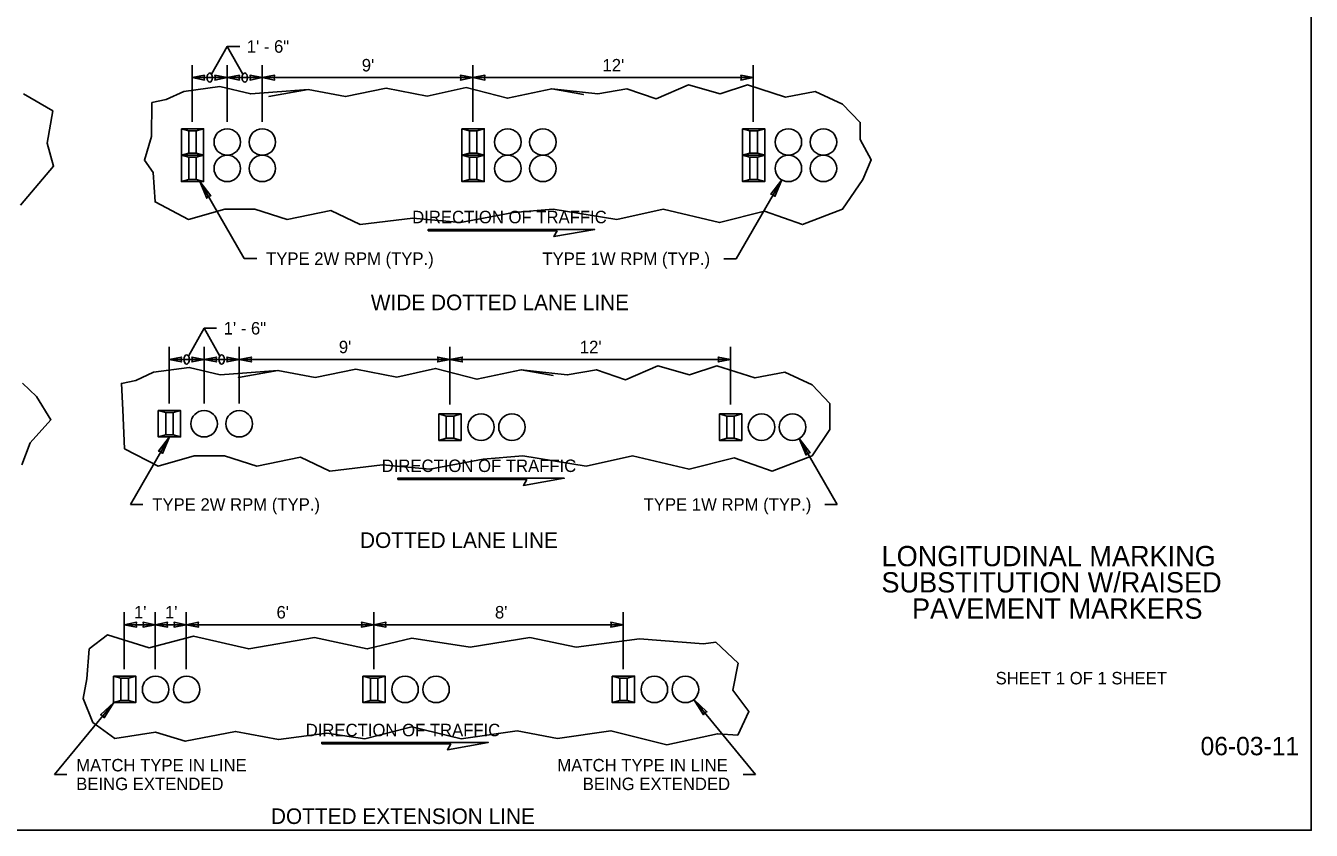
# Model space of a CAD drawing. Extents: x 99862 to 103151, y 100000 to 102076.
# Drawn here: x 101501 to 103151, y 100000 to 101032 of the extents above; entities that cross this region are included whole.
import ezdxf

# ---------------------------------------------------------------- set-up
doc = ezdxf.new("R2010")
doc.units = 0
for name, color, linetype in [('Level 1', 7, 'Continuous'), ('Level 11', 7, 'Continuous'), ('Level 15', 7, 'Continuous'), ('Level 20', 7, 'Continuous'), ('Level 3', 7, 'Continuous'), ('Level 50', 7, 'Continuous'), ('Level 62', 7, 'Continuous')]:
    doc.layers.add(name, color=color, linetype=linetype)

msp = doc.modelspace()

# ---------------------------------------------------------------- linework, layer by layer
at = {"layer": 'Level 1'}
msp.add_lwpolyline([(99862, 99999.5), (103151, 99999.5), (103151, 102075.5), (99862, 102075.5)], close=True, dxfattribs=at)
at = {"layer": 'Level 11'}
for p, q in [((101701.2, 100900), (101710.7, 100897.3)), ((101720.2, 100897.3), (101729.7, 100900)), ((102061.2, 100900), (102070.7, 100897.3)), ((102080.2, 100897.3), (102089.7, 100900)), ((102421.2, 100900), (102430.7, 100897.3)), ((102440.2, 100897.3), (102449.7, 100900)), ((101710.7, 100868.8), (101701.2, 100866.1)), ((101710.7, 100863.4), (101701.2, 100866.1)), ((101701.2, 100866.1), (101729.7, 100866.1)), ((101720.2, 100868.8), (101729.7, 100866.1)), ((101720.2, 100863.4), (101729.7, 100866.1)), ((102070.7, 100868.8), (102061.2, 100866.1)), ((102070.7, 100863.4), (102061.2, 100866.1)), ((102061.2, 100866.1), (102089.7, 100866.1)), ((102080.2, 100868.8), (102089.7, 100866.1)), ((102080.2, 100863.4), (102089.7, 100866.1)), ((102430.7, 100868.8), (102421.2, 100866.1)), ((102430.7, 100863.4), (102421.2, 100866.1)), ((102421.2, 100866.1), (102449.7, 100866.1)), ((102440.2, 100868.8), (102449.7, 100866.1)), ((102440.2, 100863.4), (102449.7, 100866.1)), ((101710.7, 100834.8), (101701.2, 100832.1)), ((101720.2, 100834.8), (101729.7, 100832.1)), ((102070.7, 100834.8), (102061.2, 100832.1)), ((102080.2, 100834.8), (102089.7, 100832.1)), ((102430.7, 100834.8), (102421.2, 100832.1)), ((102440.2, 100834.8), (102449.7, 100832.1)), ((101671.5, 100538.3), (101681.1, 100535.7)), ((101690.6, 100535.7), (101700.1, 100538.3)), ((102031.5, 100533.9), (102041.1, 100531.2)), ((102050.6, 100531.2), (102060.1, 100533.9)), ((102391.5, 100533.9), (102401.1, 100531.2)), ((102410.6, 100531.2), (102420.1, 100533.9)), ((101681.1, 100507.1), (101671.5, 100504.4)), ((101690.6, 100507.1), (101700.1, 100504.4)), ((102041.1, 100502.7), (102031.5, 100500)), ((102050.6, 100502.7), (102060.1, 100500)), ((102401.1, 100502.7), (102391.5, 100500)), ((102410.6, 100502.7), (102420.1, 100500)), ((101614.1, 100197.4), (101623.6, 100194.7)), ((101633.1, 100194.7), (101642.6, 100197.4)), ((101934.1, 100197.4), (101943.6, 100194.7)), ((101953.1, 100194.7), (101962.6, 100197.4)), ((102254.1, 100197.4), (102263.6, 100194.7)), ((102273.1, 100194.7), (102282.6, 100197.4)), ((101623.6, 100166.2), (101614.1, 100163.5)), ((101633.1, 100166.2), (101642.6, 100163.5)), ((101943.6, 100166.2), (101934.1, 100163.5)), ((101953.1, 100166.2), (101962.6, 100163.5)), ((102263.6, 100166.2), (102254.1, 100163.5)), ((102273.1, 100166.2), (102282.6, 100163.5))]:
    msp.add_line(p, q, dxfattribs=at)
for points in [[(101701.2, 100900), (101729.7, 100900), (101729.7, 100832.1), (101701.2, 100832.1)], [(101710.7, 100897.3), (101720.2, 100897.3), (101720.2, 100868.8), (101710.7, 100868.8)], [(102061.2, 100900), (102089.7, 100900), (102089.7, 100832.1), (102061.2, 100832.1)], [(102070.7, 100897.3), (102080.2, 100897.3), (102080.2, 100868.8), (102070.7, 100868.8)], [(102421.2, 100900), (102449.7, 100900), (102449.7, 100832.1), (102421.2, 100832.1)], [(102430.7, 100897.3), (102440.2, 100897.3), (102440.2, 100868.8), (102430.7, 100868.8)], [(101710.7, 100834.8), (101720.2, 100834.8), (101720.2, 100863.4), (101710.7, 100863.4)], [(102070.7, 100834.8), (102080.2, 100834.8), (102080.2, 100863.4), (102070.7, 100863.4)], [(102430.7, 100834.8), (102440.2, 100834.8), (102440.2, 100863.4), (102430.7, 100863.4)], [(101671.5, 100538.3), (101700.1, 100538.3), (101700.1, 100504.4), (101671.5, 100504.4)], [(101681.1, 100535.7), (101690.6, 100535.7), (101690.6, 100507.1), (101681.1, 100507.1)], [(102031.5, 100533.9), (102060.1, 100533.9), (102060.1, 100500), (102031.5, 100500)], [(102041.1, 100531.2), (102050.6, 100531.2), (102050.6, 100502.7), (102041.1, 100502.7)], [(102391.5, 100533.9), (102420.1, 100533.9), (102420.1, 100500), (102391.5, 100500)], [(102401.1, 100531.2), (102410.6, 100531.2), (102410.6, 100502.7), (102401.1, 100502.7)], [(101614.1, 100197.4), (101642.6, 100197.4), (101642.6, 100163.5), (101614.1, 100163.5)], [(101623.6, 100194.7), (101633.1, 100194.7), (101633.1, 100166.2), (101623.6, 100166.2)], [(101934.1, 100197.4), (101962.6, 100197.4), (101962.6, 100163.5), (101934.1, 100163.5)], [(101943.6, 100194.7), (101953.1, 100194.7), (101953.1, 100166.2), (101943.6, 100166.2)], [(102254.1, 100197.4), (102282.6, 100197.4), (102282.6, 100163.5), (102254.1, 100163.5)], [(102263.6, 100194.7), (102273.1, 100194.7), (102273.1, 100166.2), (102263.6, 100166.2)]]:
    msp.add_lwpolyline(points, close=True, dxfattribs=at)
for centre in [(101760, 100883), (101805, 100883), (102120, 100883), (102165, 100883), (102480, 100883), (102525, 100883), (101760, 100849.1), (101805, 100849.1), (102120, 100849.1), (102165, 100849.1), (102480, 100849.1), (102525, 100849.1), (101730.3, 100521.4), (101775.3, 100521.4), (102085.6, 100517), (102125.3, 100517), (102445.6, 100517), (102485.3, 100517), (101668.1, 100180.4), (101707.9, 100180.4), (101988.1, 100180.4), (102027.9, 100180.4), (102308.1, 100180.4), (102347.9, 100180.4)]:
    msp.add_circle(centre, 17, dxfattribs=at)
at = {"layer": 'Level 15'}
for p, q in [((101760, 101005.6), (101776, 101005.6)), ((101715, 100981.6), (101715, 100909)), ((101760, 100981.6), (101760, 100909)), ((101805, 100981.6), (101805, 100909)), ((102075, 100981.6), (102075, 100909)), ((102435, 100981.6), (102435, 100909)), ((101715, 100965.6), (101760, 100965.6)), ((101760, 100965.6), (101805, 100965.6)), ((101805, 100965.6), (102075, 100965.6)), ((102075, 100965.6), (102435, 100965.6)), ((101724.8, 100832.1), (101781.8, 100733.3)), ((102471.5, 100834.4), (102413, 100733.2)), ((101781.8, 100733.3), (101797.8, 100733.3)), ((102397, 100733.2), (102413, 100733.2)), ((101730.4, 100643.9), (101746.4, 100643.9)), ((101685.3, 100619.9), (101685.3, 100547.3)), ((101730.3, 100619.9), (101730.3, 100547.3)), ((101775.3, 100619.9), (101775.3, 100547.3)), ((102045.8, 100619.9), (102045.8, 100545.9)), ((102405.8, 100619.9), (102405.8, 100545.9)), ((101685.3, 100603.9), (101730.3, 100603.9)), ((101730.3, 100603.9), (101775.3, 100603.9)), ((101775.3, 100603.9), (102045.8, 100603.9)), ((102045.8, 100603.9), (102405.8, 100603.9)), ((101685.8, 100504.4), (101635.8, 100417.7)), ((102493.8, 100502.4), (102542.6, 100417.8)), ((101635.8, 100417.7), (101651.8, 100417.7)), ((102542.6, 100417.8), (102526.6, 100417.8)), ((101627.9, 100279.4), (101627.9, 100206.4)), ((101667.6, 100279.4), (101667.6, 100206.4)), ((101707.4, 100279.4), (101707.4, 100206.4)), ((101947.9, 100279.4), (101947.9, 100206.4)), ((102267.9, 100279.4), (102267.9, 100206.4)), ((101627.9, 100263.4), (101667.6, 100263.4)), ((101667.6, 100263.4), (101707.4, 100263.4)), ((101707.4, 100263.4), (101947.9, 100263.4)), ((101947.9, 100263.4), (102267.9, 100263.4)), ((102438, 100071.1), (102358.7, 100167.4)), ((101538.2, 100071.1), (101614.4, 100163.5)), ((101554.2, 100071.1), (101538.2, 100071.1)), ((102422, 100071.1), (102438, 100071.1))]:
    msp.add_line(p, q, dxfattribs=at)
for points in [[(101739.9, 100969.9), (101760, 101005.6), (101780.1, 100969.9)], [(101710.3, 100608.2), (101730.4, 100643.9), (101750.4, 100608.2)]]:
    msp.add_lwpolyline(points, dxfattribs=at)
for points in [[(101715, 100965.6), (101730.7, 100962.5), (101730, 100965.6), (101730.7, 100968.7)], [(101760, 100965.6), (101744.2, 100962.5), (101745, 100965.6), (101744.2, 100968.7)], [(101760, 100965.6), (101775.7, 100962.5), (101775, 100965.6), (101775.7, 100968.7)], [(101805, 100965.6), (101789.2, 100962.5), (101790, 100965.6), (101789.2, 100968.7)], [(101805, 100965.6), (101820.7, 100962.5), (101820, 100965.6), (101820.7, 100968.7)], [(102075, 100965.6), (102059.2, 100968.7), (102060, 100965.6), (102059.2, 100962.5)], [(102075, 100965.6), (102090.7, 100962.5), (102090, 100965.6), (102090.7, 100968.7)], [(102435, 100965.6), (102419.2, 100968.7), (102420, 100965.6), (102419.2, 100962.5)], [(101724.8, 100832.1), (101738.8, 100813.9), (101735.6, 100813.3), (101733.6, 100810.9)], [(102471.5, 100834.4), (102457.5, 100816.1), (102460.6, 100815.6), (102462.7, 100813.2)], [(101685.3, 100603.9), (101701.1, 100600.8), (101700.3, 100603.9), (101701.1, 100607)], [(101730.3, 100603.9), (101714.6, 100600.8), (101715.3, 100603.9), (101714.6, 100607)], [(101730.3, 100603.9), (101746.1, 100600.8), (101745.3, 100603.9), (101746.1, 100607)], [(101775.3, 100603.9), (101759.6, 100600.8), (101760.3, 100603.9), (101759.6, 100607)], [(101775.3, 100603.9), (101791.1, 100600.8), (101790.3, 100603.9), (101791.1, 100607)], [(102045.8, 100603.9), (102030.1, 100607), (102030.8, 100603.9), (102030.1, 100600.8)], [(102045.8, 100603.9), (102061.5, 100600.8), (102060.8, 100603.9), (102061.5, 100607)], [(102405.8, 100603.9), (102390.1, 100607), (102390.8, 100603.9), (102390.1, 100600.8)], [(101685.8, 100504.4), (101671.8, 100486.1), (101674.9, 100485.6), (101677, 100483.2)], [(102493.8, 100502.4), (102502.7, 100481.1), (102504.7, 100483.5), (102507.8, 100484.1)], [(101627.9, 100263.4), (101643.6, 100260.3), (101642.9, 100263.4), (101643.6, 100266.5)], [(101667.6, 100263.4), (101651.9, 100260.3), (101652.6, 100263.4), (101651.9, 100266.5)], [(101667.6, 100263.4), (101683.4, 100260.3), (101682.6, 100263.4), (101683.4, 100266.5)], [(101707.4, 100263.4), (101691.7, 100260.3), (101692.4, 100263.4), (101691.7, 100266.5)], [(101707.4, 100263.4), (101723.1, 100260.3), (101722.4, 100263.4), (101723.1, 100266.5)], [(101947.9, 100263.4), (101932.1, 100266.5), (101932.9, 100263.4), (101932.1, 100260.3)], [(101947.9, 100263.4), (101963.6, 100260.3), (101962.9, 100263.4), (101963.6, 100266.5)], [(102267.9, 100263.4), (102252.1, 100266.5), (102252.9, 100263.4), (102252.1, 100260.3)], [(102358.7, 100167.4), (102370.9, 100147.8), (102372.5, 100150.6), (102375.5, 100151.6)], [(101614.4, 100163.5), (101597.5, 100147.8), (101600.5, 100146.7), (101602.1, 100144)]]:
    msp.add_lwpolyline(points, close=True, dxfattribs=at)
for centre in [(101737.5, 100965.6), (101782.5, 100965.6), (101707.8, 100603.9), (101752.8, 100603.9)]:
    msp.add_ellipse(centre, major_axis=(0, 6), ratio=0.57735, dxfattribs=at)
at = {"layer": 'Level 3'}
for points in [[(102017.8, 100768.9), (102183.3, 100768.9), (102179.1, 100761.5), (102231.5, 100770.7), (102017.8, 100770.7)], [(101978.7, 100449.6), (102144.3, 100449.6), (102140, 100442.2), (102192.5, 100451.4), (101978.7, 100451.4)], [(101881.2, 100110.3), (102046.8, 100110.3), (102042.5, 100102.9), (102095, 100112.2), (101881.2, 100112.2)]]:
    msp.add_lwpolyline(points, close=True, dxfattribs=at)
at = {"layer": 'Level 50'}
for points in [[(101494.8, 100802), (101537.1, 100852.1), (101529, 100881.4), (101536.3, 100922.9), (101498.7, 100944.7)], [(101496.6, 100468.4), (101506.9, 100496.7), (101533.8, 100526.4), (101515.1, 100556.5), (101497.2, 100573.6)]]:
    msp.add_lwpolyline(points, dxfattribs=at)
for points in [[(101681.8, 100937.6), (101663.3, 100933.7), (101662.7, 100890), (101653.7, 100859.5), (101665.1, 100844), (101667.4, 100806), (101710.4, 100783.6), (101756.8, 100796.6), (101795.4, 100796.6), (101795.4, 100796.6), (101837, 100783.6), (101893.1, 100795), (101930.6, 100777.1), (101998.1, 100785.2), (102059.2, 100779.5), (102127.5, 100792.6), (102178.3, 100796.6), (102178.3, 100796.6), (102259.7, 100783.6), (102319.2, 100796.6), (102391.6, 100779.5), (102449.4, 100794.2), (102498.2, 100777.1), (102549.5, 100796.6), (102575.5, 100834.9), (102586.3, 100860.3), (102572.3, 100886.2), (102572.3, 100908.1), (102549.5, 100931.7), (102514.5, 100948), (102476.2, 100940.7), (102427.4, 100956.2), (102392.4, 100944.8), (102351.7, 100956.2), (102310.2, 100938.3), (102272.8, 100951.3), (102235.3, 100944.8), (102176.4, 100951.3), (102217.1, 100943.9), (102176.4, 100951.3), (102119.4, 100939.1), (102066.5, 100952.9), (102016.7, 100942), (101964, 100952), (101911.7, 100941.4), (101864, 100950.3), (101813.4, 100941.5), (101864, 100950.3), (101790.1, 100944.7), (101750.3, 100954.2), (101704.3, 100948)], [(101642.7, 100577), (101624.2, 100573.1), (101626, 100539.3), (101626, 100539.3), (101626, 100539.3), (101628.3, 100489.3), (101671.3, 100467), (101717.7, 100480), (101756.3, 100480), (101756.3, 100480), (101797.9, 100467), (101854, 100478.3), (101891.5, 100460.4), (101959, 100468.6), (102020.1, 100462.9), (102088.4, 100475.9), (102139.2, 100480), (102139.2, 100480), (102220.6, 100467), (102280.1, 100480), (102352.5, 100462.9), (102410.3, 100477.5), (102459.1, 100460.4), (102510.4, 100480), (102533.2, 100513.9), (102533.2, 100513.9), (102533.2, 100513.9), (102533.2, 100547.5), (102510.4, 100571.1), (102475.4, 100587.4), (102437.1, 100580.1), (102388.3, 100595.5), (102353.3, 100584.1), (102312.6, 100595.5), (102271.1, 100577.6), (102233.7, 100590.6), (102196.2, 100584.1), (102137.3, 100590.6), (102178, 100583.3), (102137.3, 100590.6), (102080.3, 100578.4), (102027.4, 100592.3), (101977.6, 100581.3), (101924.9, 100591.3), (101872.6, 100580.8), (101824.9, 100589.7), (101774.3, 100580.9), (101824.9, 100589.7), (101751, 100584.1), (101711.2, 100593.6), (101665.2, 100587.4)], [(102415, 100121.8), (102429.4, 100151.9), (102408.7, 100179.5), (102415.6, 100214), (102386.9, 100241), (102371.1, 100238.8), (102288.9, 100245.3), (102207.5, 100234.7), (102148.1, 100246.9), (102071.5, 100234.7), (101996.7, 100246.1), (101939.7, 100232.3), (101872.1, 100246.9), (101787.5, 100232.3), (101716.7, 100248.6), (101659.7, 100233.9), (101606.3, 100250.5), (101582.7, 100232.3), (101579.9, 100194), (101575, 100168.8), (101587.6, 100137.9), (101615.7, 100117.5), (101667.8, 100125.6), (101706.2, 100113.9), (101770.4, 100126.4), (101825.7, 100116), (101887.6, 100124), (101936.4, 100116.9), (101996.7, 100132.2), (102060.2, 100116.9), (102131.8, 100127.3), (102183.9, 100117.5), (102252.2, 100127.3), (102323.9, 100109.4), (102389, 100123.5)]]:
    msp.add_lwpolyline(points, close=True, dxfattribs=at)

# ---------------------------------------------------------------- texts
at = {"layer": 'Level 15'}
msp.add_text('06-03-11', height=23.62, dxfattribs=at).set_placement((103008.9, 100095.8))
at = {"layer": 'Level 20'}
for s, height, p in [('1\' - 6"', 16, (101785, 100997.6)), ('DIRECTION OF TRAFFIC', 16, (101997.3, 100778.7)), ('TYPE 2W RPM (TYP.)', 16, (101809.8, 100725.3)), ('TYPE 1W RPM (TYP.)', 16, (102164.4, 100725.2)), ('WIDE DOTTED LANE LINE', 20, (101944.2, 100667.1)), ('1\' - 6"', 16, (101755.4, 100635.9)), ('DIRECTION OF TRAFFIC', 16, (101958.2, 100459.4)), ('TYPE 2W RPM (TYP.)', 16, (101663.8, 100409.7)), ('DOTTED LANE LINE', 20, (101930.3, 100361.9)), ('DIRECTION OF TRAFFIC', 16, (101860.7, 100120.2)), ('MATCH TYPE IN LINE', 16, (101566.2, 100075.1)), ('MATCH TYPE IN LINE', 16, (102183.6, 100075.1)), ('BEING EXTENDED', 16, (101566.2, 100051.1)), ('BEING EXTENDED', 16, (102216.2, 100051.1)), ('DOTTED EXTENSION LINE', 20, (101816, 100007.6))]:
    msp.add_text(s, height=height, dxfattribs=at).set_placement(p)
for s, rotation, p in [("9'", 0, (101932.6, 100973.6)), ("12'", 0, (102241.5, 100973.6)), ("9'", 0, (101903.2, 100611.9)), ("12'", 0, (102212.4, 100611.9)), ('TYPE 1W RPM (TYP.)', 360, (102294.3, 100409.8)), ("1'", 0, (101640.3, 100271.4)), ("1'", 0, (101680.1, 100271.4)), ("6'", 0, (101823.2, 100271.4)), ("8'", 0, (102103.5, 100271.4))]:
    msp.add_text(s, height=16, rotation=rotation, dxfattribs=at).set_placement(p)
at = {"layer": 'Level 62'}
for s, height, p in [('LONGITUDINAL MARKING', 26, (102599.6, 100338.5)), ('SUBSTITUTION W/RAISED', 26, (102599.4, 100304.8)), ('PAVEMENT MARKERS', 26, (102638.6, 100271.1)), ('SHEET 1 OF 1 SHEET', 16, (102745.9, 100186.8))]:
    msp.add_text(s, height=height, dxfattribs=at).set_placement(p)

doc.saveas('drawing.dxf')
